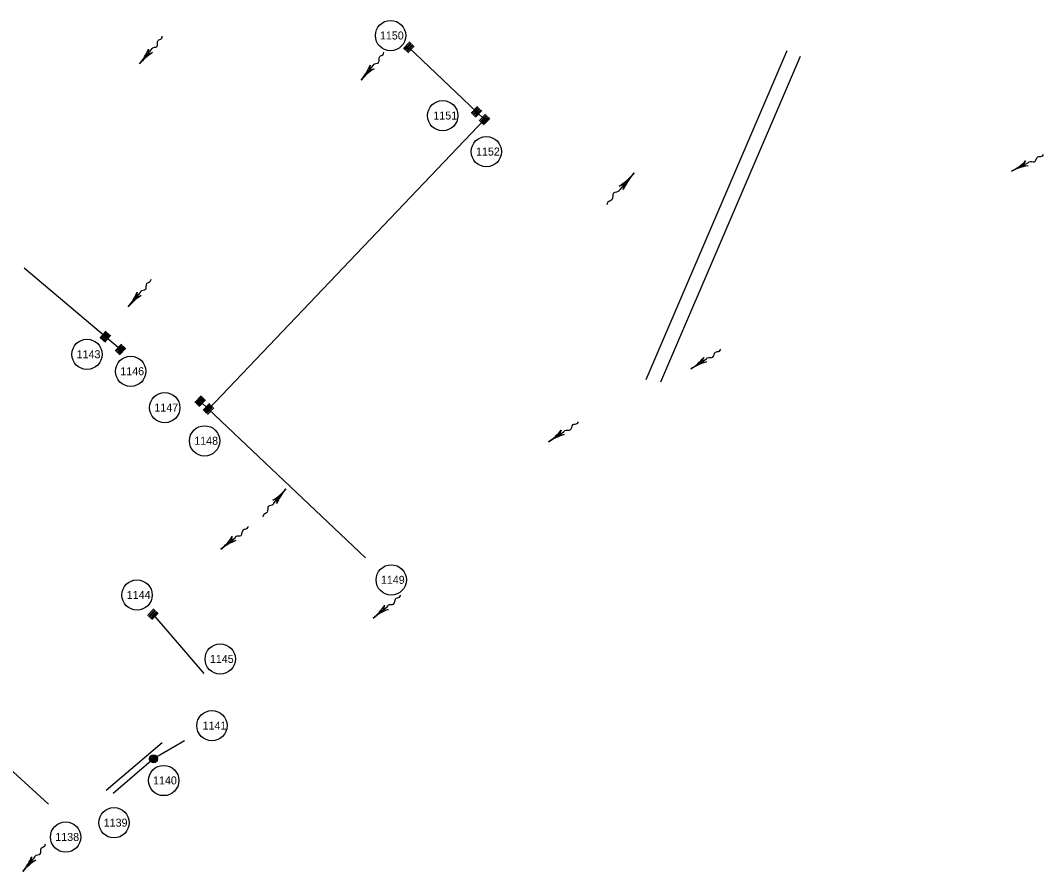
# Model space of a CAD drawing. Extents: x 594534 to 598564, y 225861 to 236229.
# Drawn here: x 595967 to 596734, y 230025 to 230663 of the extents above; entities that cross this region are included whole.
import ezdxf

# ---------------------------------------------------------------- set-up
doc = ezdxf.new("R2010")
doc.units = 0
for name, color, linetype in [('P_DRN_Flow', 7, 'Continuous'), ('P_DRN_Inlet', 7, 'Continuous'), ('P_DRN_Pipes', 7, 'Continuous'), ('P_DRN_SS_MH', 7, 'Continuous'), ('P_DRN_SS_UG', 7, 'Continuous'), ('P_DRN_Text', 7, 'Continuous')]:
    doc.layers.add(name, color=color, linetype=linetype)

msp = doc.modelspace()

# ---------------------------------------------------------------- linework, layer by layer
at = {"layer": 'P_DRN_Flow'}
for p, q in [((596056.01, 230630.82), (596065.08, 230641.65)), ((596222.12, 230618.77), (596231.19, 230629.6)), ((596709.77, 230550.49), (596722.37, 230556.88)), ((596426.82, 230549.15), (596415.97, 230536.7)), ((596047.56, 230448.62), (596056.64, 230459.45)), ((596469.27, 230402.08), (596481.14, 230409.74)), ((596362.6, 230347.5), (596374.42, 230355.23)), ((596165.67, 230312.13), (596156.57, 230301.32)), ((596116.91, 230266.79), (596127.85, 230275.72)), ((596231.11, 230215.18), (596242.06, 230224.12)), ((595968.45, 230025.1), (595977.52, 230035.93))]:
    msp.add_line(p, q, dxfattribs=at)
for points in [[(596062.69, 230641.92), (596062.17, 230638.18), (596065.76, 230639.35)], [(596228.8, 230629.86), (596228.28, 230626.12), (596231.87, 230627.29)], [(596720.28, 230558.07), (596718.33, 230554.83), (596722.09, 230554.5)], [(596418.5, 230536.56), (596419.45, 230540.69), (596415.48, 230539.18)], [(596054.25, 230459.72), (596053.72, 230455.98), (596057.31, 230457.15)], [(596478.94, 230410.7), (596477.33, 230407.29), (596481.11, 230407.34)], [(596372.21, 230356.18), (596370.63, 230352.76), (596374.4, 230352.84)], [(596158.96, 230301.05), (596159.49, 230304.79), (596155.9, 230303.62)], [(596125.56, 230276.43), (596124.34, 230272.86), (596128.09, 230273.33)], [(596239.76, 230224.83), (596238.55, 230221.25), (596242.29, 230221.73)], [(595975.13, 230036.2), (595974.61, 230032.46), (595978.2, 230033.63)]]:
    msp.add_lwpolyline(points, dxfattribs=at)
for centre, start, end in [((596023.84, 230657.77), 320.04245, 337.80477), ((596088.17, 230603.88), 122.28013, 140.04245), ((596189.96, 230645.71), 320.04245, 337.80477), ((596254.28, 230591.82), 122.28013, 140.04245), ((596690.79, 230587.91), 296.90272, 314.66504), ((596728.76, 230513.07), 99.1404, 116.90272), ((596015.4, 230475.57), 320.04245, 337.80477), ((596079.72, 230421.68), 122.28013, 140.04245), ((596446.52, 230437.33), 302.84119, 320.60351), ((596492.02, 230366.83), 105.07887, 122.84119), ((596339.64, 230382.62), 303.17379, 320.93611), ((596385.56, 230312.39), 105.41147, 123.17379), ((596133.57, 230339.14), 302.15827, 319.92058), ((596197.77, 230285.12), 139.92058, 157.6829), ((596090.38, 230299.29), 309.22223, 326.98455), ((596143.44, 230234.28), 111.45991, 129.22223), ((596204.58, 230247.69), 309.22223, 326.98455), ((596257.64, 230182.68), 111.45991, 129.22223), ((595936.29, 230052.05), 320.04245, 337.80477), ((596000.61, 229998.16), 122.28013, 140.04245)]:
    msp.add_arc(centre, 41.96, start, end, dxfattribs=at)
for centre, major_axis, start_param, end_param in [((596395.2, 230576.72), (32.24, 36.97), 4.402378, 4.712389), ((596458.45, 230521.57), (-32.24, -36.97), 4.712389, 5.0224)]:
    msp.add_ellipse(centre, major_axis=major_axis, ratio=0.855329, start_param=start_param, end_param=end_param, dxfattribs=at)
for points in [[(596065.08, 230641.65), (596065.34, 230642.46), (596069.1, 230644.01), (596069.94, 230648.43), (596072.48, 230649.99), (596073.1, 230651.72)], [(596231.19, 230629.6), (596231.45, 230630.4), (596235.22, 230631.96), (596236.05, 230636.38), (596238.59, 230637.94), (596239.22, 230639.66)], [(596722.37, 230556.88), (596722.93, 230557.52), (596727, 230557.47), (596729.51, 230561.21), (596732.45, 230561.65), (596733.71, 230562.99)], [(596415.97, 230536.7), (596415.6, 230535.8), (596411.41, 230533.86), (596410.05, 230528.96), (596407.17, 230527.09), (596406.31, 230525.15)], [(596056.64, 230459.45), (596056.9, 230460.26), (596060.66, 230461.82), (596061.5, 230466.23), (596064.03, 230467.8), (596064.66, 230469.52)], [(596481.14, 230409.74), (596481.63, 230410.43), (596485.68, 230410.81), (596487.79, 230414.78), (596490.68, 230415.52), (596491.79, 230416.99)], [(596374.42, 230355.23), (596374.91, 230355.93), (596378.96, 230356.33), (596381.04, 230360.31), (596383.92, 230361.07), (596385.03, 230362.54)], [(596156.57, 230301.32), (596156.31, 230300.52), (596152.54, 230298.97), (596151.7, 230294.55), (596149.16, 230292.99), (596148.53, 230291.27)], [(596127.85, 230275.72), (596128.26, 230276.46), (596132.25, 230277.28), (596133.9, 230281.47), (596136.69, 230282.52), (596137.63, 230284.1)], [(596242.06, 230224.12), (596242.47, 230224.86), (596246.46, 230225.68), (596248.11, 230229.86), (596250.89, 230230.92), (596251.83, 230232.5)], [(595977.52, 230035.93), (595977.78, 230036.73), (595981.55, 230038.29), (595982.38, 230042.71), (595984.92, 230044.27), (595985.55, 230046)]]:
    msp.add_spline(points, degree=3, dxfattribs=at)
at = {"layer": 'P_DRN_Inlet'}
for p, q in [((596253.88, 230642.38), (596258.65, 230647.33)), ((596254.52, 230641.75), (596259.29, 230646.7)), ((596255.17, 230641.13), (596259.94, 230646.08)), ((596255.82, 230640.5), (596260.59, 230645.45)), ((596256.47, 230639.88), (596261.24, 230644.83)), ((596257.12, 230639.25), (596261.89, 230644.21)), ((596304.53, 230594.04), (596309.28, 230599.01)), ((596305.18, 230593.42), (596309.93, 230598.39)), ((596305.83, 230592.8), (596310.58, 230597.77)), ((596306.48, 230592.18), (596311.23, 230597.15)), ((596307.14, 230591.55), (596311.88, 230596.53)), ((596307.79, 230590.93), (596312.53, 230595.91)), ((596310.68, 230588.17), (596315.43, 230593.15)), ((596311.33, 230587.55), (596316.08, 230592.53)), ((596311.98, 230586.93), (596316.73, 230591.9)), ((596312.63, 230586.31), (596317.38, 230591.28)), ((596313.29, 230585.69), (596318.03, 230590.66)), ((596313.94, 230585.07), (596318.68, 230590.04)), ((596026.53, 230425.08), (596031, 230430.31)), ((596027.21, 230424.5), (596031.68, 230429.72)), ((596027.9, 230423.91), (596032.37, 230429.14)), ((596028.58, 230423.33), (596033.05, 230428.55)), ((596029.27, 230422.74), (596033.73, 230427.97)), ((596029.95, 230422.16), (596034.42, 230427.38)), ((596037.68, 230415.74), (596042.45, 230420.69)), ((596038.33, 230415.12), (596043.1, 230420.07)), ((596038.98, 230414.49), (596043.75, 230419.44)), ((596039.63, 230413.87), (596044.39, 230418.82)), ((596040.27, 230413.24), (596045.04, 230418.2)), ((596040.92, 230412.62), (596045.69, 230417.57)), ((596097.46, 230376.97), (596102.2, 230381.94)), ((596098.11, 230376.34), (596102.85, 230381.32)), ((596098.76, 230375.72), (596103.5, 230380.7)), ((596099.41, 230375.1), (596104.16, 230380.08)), ((596100.06, 230374.48), (596104.81, 230379.46)), ((596100.71, 230373.86), (596105.46, 230378.84)), ((596103.61, 230371.1), (596108.35, 230376.07)), ((596104.26, 230370.48), (596109, 230375.45)), ((596104.91, 230369.86), (596109.65, 230374.83)), ((596105.56, 230369.24), (596110.31, 230374.21)), ((596106.21, 230368.61), (596110.96, 230373.59)), ((596106.86, 230367.99), (596111.61, 230372.97)), ((596062.06, 230217.15), (596066.8, 230222.12)), ((596062.71, 230216.53), (596067.46, 230221.5)), ((596063.36, 230215.91), (596068.11, 230220.88)), ((596064.01, 230215.28), (596068.76, 230220.26)), ((596064.67, 230214.66), (596069.41, 230219.64)), ((596065.32, 230214.04), (596070.06, 230219.02))]:
    msp.add_line(p, q, dxfattribs=at)
for points in [[(596257.91, 230641.88), (596259.3, 230643.32), (596257.86, 230644.7), (596256.47, 230643.26)], [(596308.57, 230593.56), (596309.95, 230595.01), (596308.5, 230596.39), (596307.12, 230594.94)], [(596314.72, 230587.69), (596316.1, 230589.14), (596314.65, 230590.52), (596313.27, 230589.07)], [(596030.58, 230424.82), (596031.88, 230426.34), (596030.36, 230427.64), (596029.06, 230426.12)], [(596041.71, 230415.24), (596043.1, 230416.68), (596041.66, 230418.07), (596040.27, 230416.63)], [(596101.49, 230376.49), (596102.87, 230377.93), (596101.42, 230379.31), (596100.04, 230377.87)], [(596107.64, 230370.62), (596109.02, 230372.07), (596107.57, 230373.45), (596106.19, 230372)], [(596066.09, 230216.67), (596067.47, 230218.12), (596066.03, 230219.5), (596064.65, 230218.05)]]:
    msp.add_lwpolyline(points, close=True, dxfattribs=at)
at = {"layer": 'P_DRN_Pipes'}
for p, q in [((596541.22, 230640.77), (596435.45, 230394.01)), ((596551.33, 230636.44), (596446.65, 230392.24)), ((596073.04, 230121.77), (596030.94, 230085.87))]:
    msp.add_line(p, q, dxfattribs=at)
at = {"layer": 'P_DRN_SS_MH'}
for radius in [2.98, 2.4, 1.8, 1.2, 0.6]:
    msp.add_circle((596066.55, 230109.67), radius, dxfattribs=at)
at = {"layer": 'P_DRN_SS_UG'}
for p, q in [((596257.88, 230643.29), (596308.53, 230594.97)), ((596308.53, 230594.97), (596314.68, 230589.11)), ((596314.68, 230589.11), (596107.61, 230372.03)), ((596030.47, 230426.23), (595969.51, 230477.65)), ((596041.69, 230416.66), (596030.47, 230426.23)), ((596101.46, 230377.9), (596107.61, 230372.03)), ((596107.61, 230372.03), (596225.29, 230260.53)), ((596066.06, 230218.08), (596104.18, 230173.68)), ((595901.11, 230154.51), (595987.86, 230075.53)), ((596089.66, 230123.05), (596066.55, 230109.67)), ((596066.55, 230109.67), (596036.13, 230083.72))]:
    msp.add_line(p, q, dxfattribs=at)
msp.add_lwpolyline([(596101.46, 230377.9), (596107.61, 230372.03)], dxfattribs=at)
at = {"layer": 'P_DRN_Text'}
for centre in [(596244.2, 230652.12), (596283.29, 230592.09), (596316, 230565.07), (596016.61, 230413.04), (596049.35, 230400.28), (596074.9, 230373.04), (596104.77, 230348.14), (596244.68, 230243.85), (596054.15, 230232.53), (596116.48, 230184.51), (596110.29, 230134.55), (596074.14, 230093.39), (596036.89, 230061.69), (596000.61, 230050.97)]:
    msp.add_circle(centre, 11.36, dxfattribs=at)

# ---------------------------------------------------------------- texts
for s, p in [('1150', (596236.21, 230649.21)), ('1151', (596276.31, 230589.17)), ('1152', (596308.27, 230562.15)), ('1143', (596008.88, 230410.12)), ('1146', (596041.62, 230397.36)), ('1147', (596067.16, 230370.12)), ('1148', (596097.03, 230345.22)), ('1149', (596236.95, 230240.93)), ('1144', (596046.42, 230229.61)), ('1145', (596108.75, 230181.59)), ('1141', (596103.31, 230131.63)), ('1140', (596066.14, 230090.47)), ('1139', (596029.16, 230058.78)), ('1138', (595992.87, 230048.05))]:
    msp.add_text(s, height=6, dxfattribs=at).set_placement(p)

doc.saveas('drawing.dxf')
